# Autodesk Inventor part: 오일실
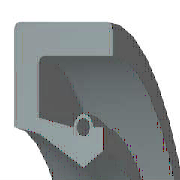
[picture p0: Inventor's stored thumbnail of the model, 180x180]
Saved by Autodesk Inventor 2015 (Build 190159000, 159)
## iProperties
IsCustomPart: 1
Created: 2015-10
Part Number: 오일실
Material: Rubber
Description: 오일-실
Document SubType Name: Modeling
Standard: KS B 2804
Designer: mdu
Standards Organization: KS
Language: ko-KR
Size Designation: S - 25 38 8
Categories: <MemberInstance><Categories><Category DisplayName="샤프트 부품" InternalName="7f7aeb1f-a693-4053-b835-cee3144e0d98" Mnemonic="SHFT"><Category DisplayName="실링" Intern
Density: 0.93 g/cm^3
Appearance: Rubber - Black - Version 1.1
Author: mdu
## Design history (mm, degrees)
revolve "본체" stored, may be unused: angle "d17" = 90 deg
revolve "스프링1" stored, may be unused: angle "d18" = 90 deg
body "Solid1"
sketch "스케치1"
  geometry: L1 (0, 19)-(8, 19); L2 (8, 19)-(8, 17.75); L3 (8, 17.75)-(1.75, 17.75); L4 (0, 19)-(0, 14.6); L5 (0, 14.6)-(1.75, 14.25); L6 (1.75, 14.25)-(4.9, 12.5); L7 (4.9, 12.5)-(0, 12.5); L8 (6.3, 13.375)-(6.3, 14.6); L9 (0, 0)-(9.586, 0) reference; L10 (4.9, 12.5)-(6.3, 13.375); L11 (0, 18)-(0, -3) reference; L12 (-1.917, 0)-(11.503, 0) reference; L13 (4.2, 14.6)-(1.75, 15.09); L14 (1.75, 15.09)-(1.75, 17.75); L15 (6.3, 14.6)-(5.6, 14.6); C1 r 0.455 at (4.9, 14.6); A1 r 0.7 centre (4.9, 14.6) between (5.6, 14.6) and (4.2, 14.6)
  constraints: 26 end point, 5 horizontal alignment, 4 perpendicular, 2 centre point, 2 collinear, 2 horizontal, 2 parallel, 2 point on circle, 2 point on line, 2 vertical alignment, 1 coincident
  dimensions: "d0" = 38 diameter of L1 L9 (= SD2); "d1" = 26.75 diameter of L8.start L9 (= ABDM); "d2" = 1.25 distance of L1.end L2.end (computed from SD); "d3" = 0.91 diameter of C1 (= SPDI); "d4" = 1.4 diameter of A1 (= SPDA); "d5" = 25 diameter of L6.end L9 (= NND); "d6" = 28.5 diameter of L5.end L9 (= TKDM); "d7" = 29.2 diameter of L4.end L9 (= HLDM); "d8" = 4.9 distance from line of C1.centre L4 (= SPDST); "d9" = 6.3 distance between parallel lines of L8 L4 (= SDI); "d10" = 8 distance between parallel lines of L2 L4 (= SWDT); "d12" = 1.75 distance between parallel lines of L14 L4 (= SD)
fillet "모깎기1" dims "d11" = 0.3 (= RR)
other parameters: "SD2" = 38 [user parameter; used in 1 equation term], "SWDT" = 8 [user parameter; used in 1 equation term], "RR" = 0.3 [user parameter; used in 1 equation term], "SD" = 1.75 [user parameter; used in 2 equation terms], "NND" = 25 [user parameter; used in 1 equation term], "SPDA" = 1.4 [user parameter; used in 1 equation term], "SPDI" = 0.91 [user parameter; used in 1 equation term], "TKDM" = 28.5 [user parameter; used in 1 equation term], "HLDM" = 29.2 [user parameter; used in 1 equation term], "ABDM" = 26.75 [user parameter; used in 1 equation term], "SDI" = 6.3 [user parameter; used in 1 equation term], "SPDST" = 4.9 [user parameter; used in 1 equation term], "d13" = 0, "d14" = 0, "d15" = 0, "LAB" = 0.35 [user parameter]
